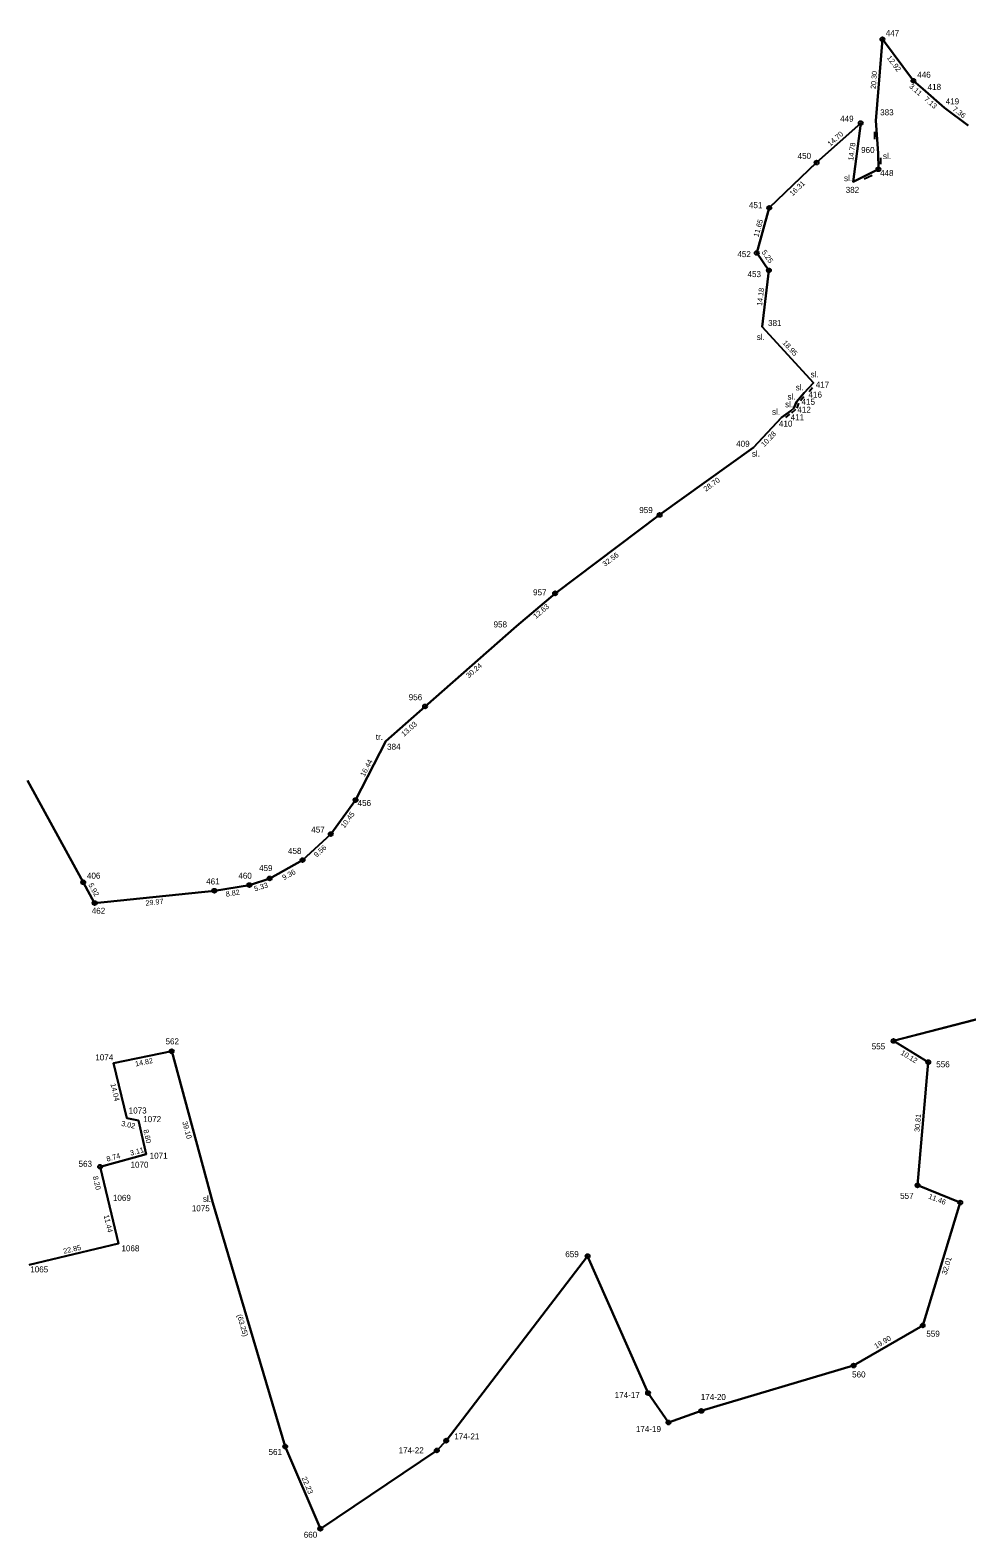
# Model space of a CAD drawing. Extents: x -555170 to -550532, y -1039598 to -1034701.
# Drawn here: x -554026.5 to -553793.6, y -1037824 to -1037449 of the extents above; entities that cross this region are included whole.
import ezdxf

# ---------------------------------------------------------------- set-up
doc = ezdxf.new("R2010")
doc.units = 0
for name, color, linetype in [('Vrstva 10', 7, 'Continuous'), ('Vrstva 40', 7, 'Continuous'), ('Vrstva 43', 7, 'Continuous'), ('Vrstva 48', 7, 'Continuous')]:
    doc.layers.add(name, color=color, linetype=linetype)

msp = doc.modelspace()

# ---------------------------------------------------------------- linework, layer by layer
at = {"layer": 'Vrstva 10'}
for p, q in [((-553816.56, -1037474.3), (-553816.54, -1037476.16)), ((-553815.05, -1037480.8), (-553815.01, -1037482.37)), ((-553817.14, -1037485.21), (-553819.13, -1037486.08)), ((-553834.11, -1037540.26), (-553834.97, -1037541.24)), ((-553831.95, -1037537.98), (-553832.82, -1037538.96)), ((-553837.65, -1037544.56), (-553838.69, -1037545.35)), ((-553836.21, -1037543.41), (-553837.19, -1037544.28)), ((-553835.46, -1037541.79), (-553835.88, -1037543.03))]:
    msp.add_line(p, q, dxfattribs=at)
at = {"layer": 'Vrstva 40'}
for p, q in [((-553814.57, -1037451.29), (-553816.21, -1037471.56)), ((-553806.85, -1037461.62), (-553814.57, -1037451.29)), ((-553804.51, -1037463.65), (-553806.85, -1037461.62)), ((-553799.13, -1037468.33), (-553804.51, -1037463.65)), ((-553793.25, -1037472.71), (-553799.13, -1037468.33)), ((-553819.96, -1037472.15), (-553830.94, -1037481.95)), ((-553821.86, -1037486.76), (-553819.96, -1037472.15)), ((-553816.21, -1037471.56), (-553815.67, -1037479.58)), ((-553815.67, -1037479.58), (-553815.57, -1037483.62)), ((-553830.94, -1037481.95), (-553842.73, -1037493.23)), ((-553815.57, -1037483.62), (-553821.86, -1037486.76)), ((-553842.73, -1037493.23), (-553845.82, -1037504.43)), ((-553845.82, -1037504.43), (-553842.81, -1037508.77)), ((-553842.81, -1037508.77), (-553844.47, -1037522.82)), ((-553844.47, -1037522.82), (-553831.71, -1037536.78)), ((-553831.71, -1037536.78), (-553834.02, -1037539.26)), ((-553835.97, -1037541.43), (-553836.58, -1037543.05)), ((-553834.02, -1037539.26), (-553835.97, -1037541.43)), ((-553837.36, -1037543.69), (-553839.66, -1037545.33)), ((-553836.58, -1037543.05), (-553837.36, -1037543.69)), ((-553839.66, -1037545.33), (-553846.66, -1037552.83)), ((-553846.66, -1037552.83), (-553869.98, -1037569.6)), ((-553869.98, -1037569.6), (-553895.97, -1037589.1)), ((-553895.97, -1037589.1), (-553905.57, -1037597.25)), ((-553905.57, -1037597.25), (-553928.31, -1037617.24)), ((-553928.31, -1037617.24), (-553938.04, -1037625.9)), ((-553938.04, -1037625.9), (-553945.6, -1037640.52)), ((-554013.33, -1037660.96), (-554027.21, -1037635.62)), ((-553945.6, -1037640.52), (-553951.76, -1037648.96)), ((-553951.76, -1037648.96), (-553958.79, -1037655.45)), ((-553958.79, -1037655.45), (-553966.96, -1037660.02)), ((-554010.49, -1037666.14), (-554013.33, -1037660.96)), ((-553966.96, -1037660.02), (-553972, -1037661.66)), ((-553980.71, -1037663.07), (-554010.49, -1037666.14)), ((-553972, -1037661.66), (-553980.71, -1037663.07)), ((-553811.81, -1037700.43), (-553736.67, -1037680.93)), ((-553803.16, -1037705.71), (-553811.81, -1037700.43)), ((-554005.84, -1037705.93), (-553991.33, -1037702.98)), ((-554002.49, -1037719.62), (-554005.84, -1037705.93)), ((-553991.33, -1037702.98), (-553981.07, -1037740.66)), ((-553805.84, -1037736.34), (-553803.16, -1037705.71)), ((-553999.57, -1037720.24), (-554002.49, -1037719.62)), ((-553997.7, -1037728.63), (-553999.57, -1037720.24)), ((-554000.69, -1037729.44), (-553997.7, -1037728.63)), ((-554009.13, -1037731.73), (-554000.69, -1037729.44)), ((-554007.22, -1037739.73), (-554009.13, -1037731.73)), ((-553795.21, -1037740.63), (-553805.84, -1037736.34)), ((-554004.57, -1037750.84), (-554007.22, -1037739.73)), ((-553981.07, -1037740.66), (-553963.1, -1037801.3)), ((-553804.53, -1037771.2), (-553795.21, -1037740.63)), ((-554026.81, -1037756.1), (-554004.57, -1037750.84)), ((-553923.06, -1037799.85), (-553887.88, -1037753.95)), ((-553887.88, -1037753.95), (-553872.85, -1037788)), ((-553821.75, -1037781.17), (-553804.53, -1037771.2)), ((-553859.61, -1037792.46), (-553821.75, -1037781.17)), ((-553872.85, -1037788), (-553867.77, -1037795.33)), ((-553867.77, -1037795.33), (-553859.61, -1037792.46)), ((-553925.39, -1037802.29), (-553923.06, -1037799.85)), ((-553963.1, -1037801.3), (-553954.36, -1037821.74)), ((-553954.36, -1037821.74), (-553925.39, -1037802.29))]:
    msp.add_line(p, q, dxfattribs=at)
at = {"layer": 'Vrstva 43'}
for p, q in [((-553814.57, -1037451.29), (-553814.57, -1037451.29)), ((-553806.85, -1037461.62), (-553806.85, -1037461.62)), ((-553804.51, -1037463.65), (-553804.51, -1037463.65)), ((-553799.13, -1037468.33), (-553799.13, -1037468.33)), ((-553819.96, -1037472.15), (-553819.96, -1037472.15)), ((-553816.21, -1037471.56), (-553816.21, -1037471.56)), ((-553815.67, -1037479.58), (-553815.67, -1037479.58)), ((-553830.94, -1037481.95), (-553830.94, -1037481.95)), ((-553815.57, -1037483.62), (-553815.57, -1037483.62)), ((-553821.86, -1037486.76), (-553821.86, -1037486.76)), ((-553842.73, -1037493.23), (-553842.73, -1037493.23)), ((-553845.82, -1037504.43), (-553845.82, -1037504.43)), ((-553842.81, -1037508.77), (-553842.81, -1037508.77)), ((-553844.47, -1037522.82), (-553844.47, -1037522.82)), ((-553831.71, -1037536.78), (-553831.71, -1037536.78)), ((-553835.97, -1037541.43), (-553835.97, -1037541.43)), ((-553834.02, -1037539.26), (-553834.02, -1037539.26)), ((-553837.36, -1037543.69), (-553837.36, -1037543.69)), ((-553836.58, -1037543.05), (-553836.58, -1037543.05)), ((-553839.66, -1037545.33), (-553839.66, -1037545.33)), ((-553846.66, -1037552.83), (-553846.66, -1037552.83)), ((-553869.98, -1037569.6), (-553869.98, -1037569.6)), ((-553895.97, -1037589.1), (-553895.97, -1037589.1)), ((-553905.57, -1037597.25), (-553905.57, -1037597.25)), ((-553928.31, -1037617.24), (-553928.31, -1037617.24)), ((-553938.04, -1037625.9), (-553938.04, -1037625.9)), ((-553945.6, -1037640.52), (-553945.6, -1037640.52)), ((-553951.76, -1037648.96), (-553951.76, -1037648.96)), ((-553958.79, -1037655.45), (-553958.79, -1037655.45)), ((-554013.33, -1037660.96), (-554013.33, -1037660.96)), ((-553966.96, -1037660.02), (-553966.96, -1037660.02)), ((-553980.71, -1037663.07), (-553980.71, -1037663.07)), ((-553972, -1037661.66), (-553972, -1037661.66)), ((-554010.49, -1037666.14), (-554010.49, -1037666.14)), ((-553811.81, -1037700.43), (-553811.81, -1037700.43)), ((-554005.84, -1037705.93), (-554005.84, -1037705.93)), ((-553991.33, -1037702.98), (-553991.33, -1037702.98)), ((-553803.16, -1037705.71), (-553803.16, -1037705.71)), ((-554002.49, -1037719.62), (-554002.49, -1037719.62)), ((-553999.57, -1037720.24), (-553999.57, -1037720.24)), ((-553997.7, -1037728.63), (-553997.7, -1037728.63)), ((-554009.13, -1037731.73), (-554009.13, -1037731.73)), ((-554000.69, -1037729.44), (-554000.69, -1037729.44)), ((-553805.84, -1037736.34), (-553805.84, -1037736.34)), ((-554007.22, -1037739.73), (-554007.22, -1037739.73)), ((-553981.07, -1037740.66), (-553981.07, -1037740.66)), ((-553795.21, -1037740.63), (-553795.21, -1037740.63)), ((-554004.57, -1037750.84), (-554004.57, -1037750.84)), ((-553887.88, -1037753.95), (-553887.88, -1037753.95)), ((-553804.53, -1037771.2), (-553804.53, -1037771.2)), ((-553821.75, -1037781.17), (-553821.75, -1037781.17)), ((-553872.85, -1037788), (-553872.85, -1037788)), ((-553859.61, -1037792.46), (-553859.61, -1037792.46)), ((-553867.77, -1037795.33), (-553867.77, -1037795.33)), ((-553923.06, -1037799.85), (-553923.06, -1037799.85)), ((-553963.1, -1037801.3), (-553963.1, -1037801.3)), ((-553925.39, -1037802.29), (-553925.39, -1037802.29)), ((-553954.36, -1037821.74), (-553954.36, -1037821.74))]:
    msp.add_line(p, q, dxfattribs=at)
for centre, radius in [((-553814.57, -1037451.29), 0.5), ((-553814.57, -1037451.29), 0.01), ((-553806.85, -1037461.62), 0.5), ((-553806.85, -1037461.62), 0.01), ((-553819.97, -1037472.15), 0.5), ((-553819.97, -1037472.15), 0.01), ((-553830.94, -1037481.95), 0.5), ((-553830.94, -1037481.95), 0.01), ((-553815.57, -1037483.62), 0.5), ((-553815.57, -1037483.62), 0.01), ((-553842.73, -1037493.23), 0.5), ((-553842.73, -1037493.23), 0.01), ((-553845.82, -1037504.43), 0.5), ((-553845.82, -1037504.43), 0.01), ((-553842.81, -1037508.77), 0.5), ((-553842.81, -1037508.77), 0.01), ((-553869.98, -1037569.6), 0.5), ((-553869.98, -1037569.6), 0.01), ((-553895.97, -1037589.1), 0.5), ((-553895.97, -1037589.1), 0.01), ((-553928.31, -1037617.24), 0.5), ((-553928.31, -1037617.24), 0.01), ((-553945.6, -1037640.52), 0.5), ((-553945.6, -1037640.52), 0.01), ((-553951.76, -1037648.96), 0.5), ((-553951.76, -1037648.96), 0.01), ((-553958.79, -1037655.45), 0.5), ((-553958.79, -1037655.45), 0.01), ((-554013.33, -1037660.96), 0.5), ((-554013.33, -1037660.96), 0.01), ((-553972, -1037661.66), 0.5), ((-553966.96, -1037660.02), 0.5), ((-553966.96, -1037660.02), 0.01), ((-553980.71, -1037663.07), 0.5), ((-553980.71, -1037663.07), 0.01), ((-553972, -1037661.66), 0.01), ((-554010.49, -1037666.14), 0.5), ((-554010.49, -1037666.14), 0.01), ((-553991.33, -1037702.98), 0.5), ((-553811.81, -1037700.43), 0.5), ((-553811.81, -1037700.43), 0.01), ((-553991.33, -1037702.98), 0.01), ((-553803.16, -1037705.71), 0.5), ((-553803.16, -1037705.71), 0.01), ((-554009.13, -1037731.73), 0.5), ((-554009.13, -1037731.73), 0.01), ((-553805.84, -1037736.34), 0.5), ((-553805.84, -1037736.34), 0.01), ((-553795.21, -1037740.63), 0.5), ((-553795.21, -1037740.63), 0.01), ((-553887.88, -1037753.95), 0.5), ((-553887.88, -1037753.95), 0.01), ((-553804.53, -1037771.2), 0.5), ((-553804.53, -1037771.2), 0.01), ((-553821.75, -1037781.17), 0.5), ((-553821.75, -1037781.17), 0.01), ((-553872.85, -1037788), 0.5), ((-553872.85, -1037788), 0.01), ((-553859.61, -1037792.46), 0.5), ((-553859.61, -1037792.46), 0.01), ((-553867.77, -1037795.33), 0.5), ((-553867.77, -1037795.33), 0.01), ((-553923.06, -1037799.85), 0.5), ((-553923.06, -1037799.85), 0.01), ((-553963.1, -1037801.3), 0.5), ((-553963.1, -1037801.3), 0.01), ((-553925.39, -1037802.29), 0.5), ((-553925.39, -1037802.29), 0.01), ((-553954.36, -1037821.74), 0.5), ((-553954.36, -1037821.74), 0.01)]:
    msp.add_circle(centre, radius, dxfattribs=at)
at = {"layer": 'Vrstva 48'}
for points in [[(-554027.21, -1037635.62), (-554013.33, -1037660.96), (-554010.49, -1037666.14), (-553980.71, -1037663.07), (-553972, -1037661.66), (-553966.96, -1037660.02), (-553958.79, -1037655.45), (-553951.76, -1037648.96), (-553945.6, -1037640.52), (-553938.04, -1037625.9), (-553928.31, -1037617.24), (-553905.57, -1037597.25), (-553895.97, -1037589.1), (-553869.98, -1037569.6), (-553846.66, -1037552.83), (-553839.66, -1037545.33), (-553837.36, -1037543.69), (-553836.58, -1037543.05), (-553835.97, -1037541.43), (-553834.02, -1037539.26), (-553831.71, -1037536.78), (-553844.47, -1037522.82), (-553842.81, -1037508.77), (-553845.82, -1037504.43), (-553842.73, -1037493.23), (-553830.94, -1037481.95), (-553819.96, -1037472.15), (-553821.86, -1037486.76), (-553815.57, -1037483.62), (-553815.67, -1037479.58), (-553816.21, -1037471.56), (-553814.57, -1037451.29), (-553806.85, -1037461.62), (-553804.51, -1037463.65), (-553799.13, -1037468.33), (-553793.25, -1037472.71)], [(-553736.67, -1037680.93), (-553811.81, -1037700.43), (-553803.16, -1037705.71), (-553805.84, -1037736.34), (-553795.21, -1037740.63), (-553804.53, -1037771.2), (-553821.75, -1037781.17), (-553859.61, -1037792.46), (-553867.77, -1037795.33), (-553872.85, -1037788), (-553887.88, -1037753.95), (-553923.06, -1037799.85), (-553925.39, -1037802.29), (-553954.36, -1037821.74), (-553963.1, -1037801.3), (-553981.07, -1037740.66), (-553991.33, -1037702.98), (-554005.84, -1037705.93), (-554002.49, -1037719.62), (-553999.57, -1037720.24), (-553997.7, -1037728.63), (-554000.69, -1037729.44), (-554009.13, -1037731.73), (-554007.22, -1037739.73), (-554004.57, -1037750.84), (-554026.81, -1037756.1)]]:
    msp.add_lwpolyline(points, dxfattribs=at)

# ---------------------------------------------------------------- texts
at = {"layer": 'Vrstva 10'}
for s, rotation, p in [('12.92', 306.7734, (-553813.56, -1037455.9)), ('20.30', 85.3768, (-553816.23, -1037463.71)), ('3.11', 319.0991, (-553808.03, -1037463.18)), ('7.13', 318.9804, (-553804.33, -1037466.39)), ('7.36', 323.3176, (-553797.26, -1037468.91)), ('14.70', 41.7698, (-553827.52, -1037478.02)), ('14.78', 82.615, (-553821.84, -1037481.53)), ('16.31', 43.7386, (-553836.93, -1037490.38)), ('11.65', 74.5991, (-553845.43, -1037500.59)), ('5.25', 304.7559, (-553844.68, -1037504.25)), ('14.18', 83.2638, (-553844.52, -1037517.66)), ('18.95', 312.4286, (-553839.52, -1037526.88)), ('10.28', 46.9749, (-553843.95, -1037552.8)), ('28.70', 35.7209, (-553858.48, -1037563.84)), ('32.56', 36.8858, (-553883.6, -1037582.52)), ('12.63', 40.3152, (-553900.74, -1037595.5)), ('30.24', 41.3177, (-553917.4, -1037610.25)), ('13.03', 41.6701, (-553933.53, -1037624.8)), ('16.44', 62.656, (-553943.38, -1037634.82)), ('10.45', 53.8848, (-553948.38, -1037647.64)), ('9.56', 42.7231, (-553955.27, -1037654.86)), ('5.92', 298.7118, (-554012.1, -1037661.58)), ('5.33', 18.0181, (-553970.59, -1037663.26)), ('9.36', 29.2401, (-553963.4, -1037660.48)), ('29.97', 5.8862, (-553997.77, -1037666.79)), ('8.82', 9.1678, (-553977.77, -1037664.57)), ('14.82', 11.5051, (-554000.29, -1037706.79)), ('10.12', 328.5538, (-553810.18, -1037703.71)), ('14.04', 283.7503, (-554006.57, -1037711.16)), ('3.02', 348.0125, (-554003.97, -1037721.53)), ('39.10', 285.2374, (-553988.72, -1037720.58)), ('30.81', 85.0127, (-553805.34, -1037723.12)), ('8.60', 282.565, (-553998.39, -1037722.57)), ('8.74', 15.1578, (-554007.37, -1037730.45)), ('3.11', 15.1578, (-554001.49, -1037728.98)), ('8.20', 283.4157, (-554010.96, -1037734.19)), ('11.46', 338.0255, (-553803.25, -1037739.57)), ('11.44', 283.4157, (-554008.24, -1037743.83)), ('22.85', 13.3066, (-554018.11, -1037753.38)), ('32.01', 73.0366, (-553798.63, -1037758.69)), ('(63.25)', 286.5043, (-553975.12, -1037768.62)), ('19.90', 30.0696, (-553816.15, -1037777.01)), ('22.23', 293.1579, (-553959.05, -1037809.13))]:
    msp.add_text(s, height=1.3, rotation=rotation, dxfattribs=at).set_placement(p)
at = {"layer": 'Vrstva 43'}
for s, p in [('447', (-553813.75, -1037450.52)), ('446', (-553805.91, -1037460.85)), ('418', (-553803.33, -1037463.88)), ('419', (-553798.84, -1037467.49)), ('383', (-553815.13, -1037470.21)), ('449', (-553825.09, -1037471.8)), ('450', (-553835.66, -1037481.04)), ('960', (-553819.87, -1037479.57)), ('sl.', (-553814.44, -1037481.09)), ('sl.', (-553824.12, -1037486.58)), ('448', (-553815.16, -1037485.32)), ('382', (-553823.7, -1037489.5)), ('451', (-553847.77, -1037493.3)), ('452', (-553850.64, -1037505.48)), ('453', (-553848.12, -1037510.45)), ('381', (-553843.01, -1037522.61)), ('sl.', (-553845.81, -1037526.09)), ('sl.', (-553832.43, -1037535.39)), ('sl.', (-553836.14, -1037538.63)), ('417', (-553831.16, -1037537.94)), ('sl.', (-553838.78, -1037542.83)), ('sl.', (-553838.19, -1037540.93)), ('415', (-553834.68, -1037542.2)), ('416', (-553832.95, -1037540.41)), ('sl.', (-553842.02, -1037544.69)), ('411', (-553837.39, -1037546.04)), ('412', (-553835.73, -1037544.17)), ('410', (-553840.3, -1037547.63)), ('409', (-553850.94, -1037552.65)), ('sl.', (-553847.04, -1037555.1)), ('959', (-553875.05, -1037569.14)), ('957', (-553901.46, -1037589.59)), ('958', (-553911.28, -1037597.58)), ('956', (-553932.38, -1037615.68)), ('tr.', (-553940.56, -1037625.56)), ('384', (-553937.76, -1037628)), ('456', (-553945.09, -1037641.99)), ('457', (-553956.61, -1037648.6)), ('458', (-553962.4, -1037653.9)), ('459', (-553969.6, -1037658.18)), ('406', (-554012.4, -1037660.06)), ('461', (-553982.75, -1037661.51)), ('460', (-553974.75, -1037660.08)), ('462', (-554011.21, -1037668.81)), ('562', (-553992.86, -1037701.28)), ('555', (-553817.23, -1037702.53)), ('1074', (-554010.33, -1037705.27)), ('556', (-553801.19, -1037706.98)), ('1073', (-554002.02, -1037718.48)), ('1072', (-553998.41, -1037720.63)), ('1071', (-553996.81, -1037729.73)), ('563', (-554014.49, -1037731.74)), ('1070', (-554001.56, -1037731.97)), ('1069', (-554005.94, -1037740.2)), ('sl.', (-553983.57, -1037740.45)), ('557', (-553810.17, -1037739.71)), ('1075', (-553986.32, -1037742.8)), ('1068', (-554003.82, -1037752.76)), ('659', (-553893.44, -1037754.21)), ('1065', (-554026.5, -1037758)), ('559', (-553803.65, -1037774)), ('560', (-553822.11, -1037784.13)), ('174-17', (-553881.15, -1037789.24)), ('174-20', (-553859.75, -1037789.74)), ('174-19', (-553875.88, -1037797.7)), ('174-21', (-553921.06, -1037799.55)), ('561', (-553967.24, -1037803.4)), ('174-22', (-553934.89, -1037803)), ('660', (-553958.48, -1037824))]:
    msp.add_text(s, height=1.5, dxfattribs=at).set_placement(p)

doc.saveas('drawing.dxf')
